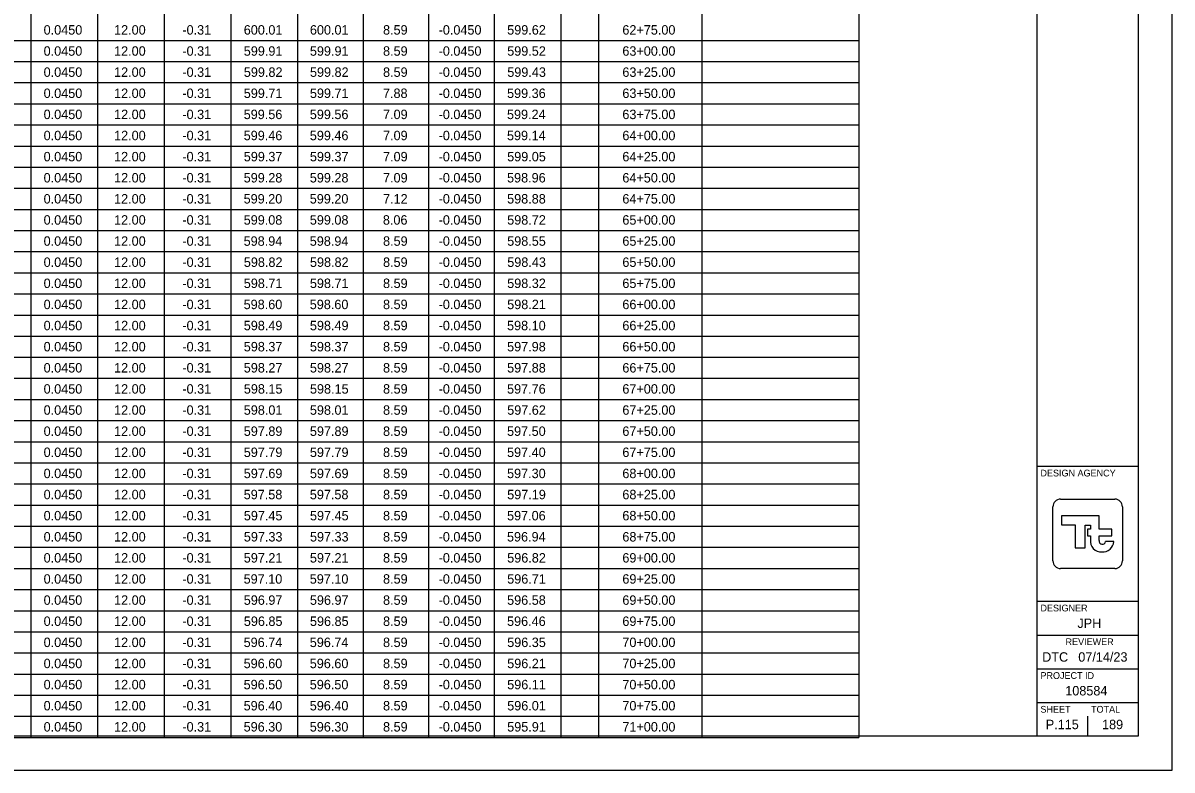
# Model space of a CAD drawing. Extents: x 0 to 34, y 0 to 22.
# Drawn here: x 16.97 to 34, y 0 to 11.07 of the extents above; entities that cross this region are included whole.
import ezdxf

# ---------------------------------------------------------------- set-up
doc = ezdxf.new("R2010")
doc.units = 0
for name, color, linetype in [('SH_Border', 7, 'Continuous'), ('SH_Cut_Line', 7, 'Continuous'), ('SH_Data', 7, 'Continuous'), ('SH_Text', 7, 'Continuous')]:
    doc.layers.add(name, color=color, linetype=linetype)

msp = doc.modelspace()

# ---------------------------------------------------------------- linework, layer by layer
at = {"layer": 'SH_Border'}
for p, q in [((32, 0.5), (32, 21.5)), ((32, 4.5), (33.5, 4.5)), ((32, 2.5), (33.5, 2.5)), ((32, 2), (33.5, 2)), ((32, 1.5), (33.5, 1.5)), ((32, 1), (33.5, 1))]:
    msp.add_line(p, q, dxfattribs=at)
msp.add_lwpolyline([(1.5, 21.5), (33.5, 21.5), (33.5, 0.5), (1.5, 0.5)], close=True, dxfattribs=at)
at = {"layer": 'SH_Cut_Line'}
msp.add_lwpolyline([(0, 0), (34, 0), (34, 22), (0, 22)], close=True, dxfattribs=at)
at = {"layer": 'SH_Data'}
for p, q in [((32.75, 3.5), (32.75, 3.5)), ((32.791, 3.415), (32.791, 3.415)), ((33.136, 3.385), (33.015, 3.385)), ((32.75, 0.5), (32.75, 0.8)), ((32.375, 0.675), (32.375, 0.675))]:
    msp.add_line(p, q, dxfattribs=at)
for points in [[(32.348, 4.014), (33.152, 4.014)], [(32.236, 3.099), (32.236, 3.901)], [(32.922, 3.399), (32.922, 3.47), (33.107, 3.47), (33.107, 3.568), (32.922, 3.568), (32.922, 3.768), (32.361, 3.768), (32.361, 3.632), (32.566, 3.632), (32.566, 3.294), (32.715, 3.294), (32.715, 3.63), (32.79, 3.63), (32.79, 3.568), (32.748, 3.568), (32.748, 3.47), (32.79, 3.47), (32.79, 3.415), (32.791, 3.415)], [(33.264, 3.901), (33.264, 3.099)], [(33.152, 2.986), (32.348, 2.986)]]:
    msp.add_lwpolyline(points, dxfattribs=at)
for centre, radius, start, end in [((32.348, 3.901), 0.113, 90, 180), ((33.152, 3.901), 0.113, 360, 90), ((32.949, 3.392), 0.16, 171.8856, 274.8323), ((32.968, 3.392), 0.0473, 171.8856, 350.9243), ((32.976, 3.392), 0.16, 265.1677, 357.3201), ((32.348, 3.099), 0.113, 180, 270), ((33.152, 3.099), 0.113, 270, 360)]:
    msp.add_arc(centre, radius, start, end, dxfattribs=at)
at = {"layer": 'SH_Text'}
for p, q in [((29.356, 21.5), (29.356, 0.484)), ((24.942, 20.396), (24.942, 0.484)), ((27.034, 20.396), (27.034, 0.484)), ((19.062, 19.853), (19.062, 0.484)), ((22.011, 19.853), (22.011, 0.484)), ((25.502, 19.853), (25.502, 0.484)), ((17.086, 19.54), (17.086, 0.484)), ((18.074, 19.54), (18.074, 0.484)), ((20.051, 19.54), (20.051, 0.484)), ((21.039, 19.54), (21.039, 0.484)), ((22.982, 19.54), (22.982, 0.484)), ((23.954, 19.54), (23.954, 0.484)), ((4.14, 10.811), (29.356, 10.811)), ((4.14, 10.498), (29.356, 10.498)), ((4.14, 10.185), (29.356, 10.185)), ((4.14, 9.872), (29.356, 9.872)), ((4.14, 9.559), (29.356, 9.559)), ((4.14, 9.246), (29.356, 9.246)), ((4.14, 8.933), (29.356, 8.933)), ((4.14, 8.62), (29.356, 8.62)), ((4.14, 8.307), (29.356, 8.307)), ((4.14, 7.994), (29.356, 7.994)), ((4.14, 7.681), (29.356, 7.681)), ((4.14, 7.368), (29.356, 7.368)), ((4.14, 7.055), (29.356, 7.055)), ((4.14, 6.742), (29.356, 6.742)), ((4.14, 6.429), (29.356, 6.429)), ((4.14, 6.116), (29.356, 6.116)), ((4.14, 5.804), (29.356, 5.804)), ((4.14, 5.491), (29.356, 5.491)), ((4.14, 5.178), (29.356, 5.178)), ((4.14, 4.865), (29.356, 4.865)), ((4.14, 4.552), (29.356, 4.552)), ((4.14, 4.239), (29.356, 4.239)), ((4.14, 3.926), (29.356, 3.926)), ((4.14, 3.613), (29.356, 3.613)), ((4.14, 3.3), (29.356, 3.3)), ((4.14, 2.987), (29.356, 2.987)), ((4.14, 2.674), (29.356, 2.674)), ((4.14, 2.361), (29.356, 2.361)), ((4.14, 2.048), (29.356, 2.048)), ((4.14, 1.735), (29.356, 1.735)), ((4.14, 1.422), (29.356, 1.422)), ((4.14, 1.109), (29.356, 1.109)), ((4.14, 0.796), (29.356, 0.796)), ((4.14, 0.484), (29.356, 0.484))]:
    msp.add_line(p, q, dxfattribs=at)

# ---------------------------------------------------------------- texts
at = {"layer": 'SH_Data'}
for s, height, p in [('DESIGN AGENCY', 0.1, (32.05, 4.35)), ('DESIGNER', 0.1, (32.05, 2.35)), ('JPH', 0.14, (32.598, 2.105)), ('REVIEWER', 0.1, (32.422, 1.85)), ('DTC', 0.14, (32.076, 1.605)), ('07/14/23', 0.14, (32.611, 1.605)), ('PROJECT ID', 0.1, (32.05, 1.35)), ('108584', 0.14, (32.418, 1.105)), ('SHEET', 0.1, (32.05, 0.85)), ('TOTAL', 0.1, (32.8, 0.85)), ('P.115', 0.14, (32.129, 0.605)), ('189', 0.14, (32.963, 0.605))]:
    msp.add_text(s, height=height, dxfattribs=at).set_placement(p)
at = {"layer": 'SH_Text'}
for s, p in [('0.0450', (17.277, 10.897)), ('12.00', (18.321, 10.897)), ('-0.31', (19.333, 10.897)), ('600.01', (20.243, 10.897)), ('600.01', (21.223, 10.897)), ('8.59', (22.307, 10.897)), ('-0.0450', (23.131, 10.897)), ('599.62', (24.147, 10.897)), ('62+75.00', (25.854, 10.897)), ('0.0450', (17.277, 10.584)), ('12.00', (18.321, 10.584)), ('-0.31', (19.333, 10.584)), ('599.91', (20.243, 10.584)), ('599.91', (21.223, 10.584)), ('8.59', (22.307, 10.584)), ('-0.0450', (23.131, 10.584)), ('599.52', (24.147, 10.584)), ('63+00.00', (25.854, 10.584)), ('0.0450', (17.277, 10.271)), ('12.00', (18.321, 10.271)), ('-0.31', (19.333, 10.271)), ('599.82', (20.244, 10.271)), ('599.82', (21.224, 10.271)), ('8.59', (22.307, 10.271)), ('-0.0450', (23.131, 10.271)), ('599.43', (24.148, 10.271)), ('63+25.00', (25.854, 10.271)), ('0.0450', (17.277, 9.958)), ('12.00', (18.321, 9.958)), ('-0.31', (19.333, 9.958)), ('599.71', (20.243, 9.958)), ('599.71', (21.223, 9.958)), ('7.88', (22.306, 9.958)), ('-0.0450', (23.131, 9.958)), ('599.36', (24.145, 9.958)), ('63+50.00', (25.854, 9.958)), ('0.0450', (17.277, 9.645)), ('12.00', (18.321, 9.645)), ('-0.31', (19.333, 9.645)), ('599.56', (20.242, 9.645)), ('599.56', (21.222, 9.645)), ('7.09', (22.307, 9.645)), ('-0.0450', (23.131, 9.645)), ('599.24', (24.144, 9.645)), ('63+75.00', (25.854, 9.645)), ('0.0450', (17.277, 9.332)), ('12.00', (18.321, 9.332)), ('-0.31', (19.333, 9.332)), ('599.46', (20.242, 9.332)), ('599.46', (21.222, 9.332)), ('7.09', (22.307, 9.332)), ('-0.0450', (23.131, 9.332)), ('599.14', (24.144, 9.332)), ('64+00.00', (25.854, 9.332)), ('0.0450', (17.277, 9.019)), ('12.00', (18.321, 9.019)), ('-0.31', (19.333, 9.019)), ('599.37', (20.243, 9.019)), ('599.37', (21.223, 9.019)), ('7.09', (22.307, 9.019)), ('-0.0450', (23.131, 9.019)), ('599.05', (24.147, 9.019)), ('64+25.00', (25.854, 9.019)), ('0.0450', (17.277, 8.706)), ('12.00', (18.321, 8.706)), ('-0.31', (19.333, 8.706)), ('599.28', (20.242, 8.706)), ('599.28', (21.222, 8.706)), ('7.09', (22.307, 8.706)), ('-0.0450', (23.131, 8.706)), ('598.96', (24.145, 8.706)), ('64+50.00', (25.854, 8.706)), ('0.0450', (17.277, 8.394)), ('12.00', (18.321, 8.394)), ('-0.31', (19.333, 8.394)), ('599.20', (20.241, 8.394)), ('599.20', (21.221, 8.394)), ('7.12', (22.307, 8.394)), ('-0.0450', (23.131, 8.394)), ('598.88', (24.146, 8.394)), ('64+75.00', (25.854, 8.394)), ('0.0450', (17.277, 8.081)), ('12.00', (18.321, 8.081)), ('-0.31', (19.333, 8.081)), ('599.08', (20.242, 8.081)), ('599.08', (21.222, 8.081)), ('8.06', (22.305, 8.081)), ('-0.0450', (23.131, 8.081)), ('598.72', (24.147, 8.081)), ('65+00.00', (25.854, 8.081)), ('0.0450', (17.277, 7.768)), ('12.00', (18.321, 7.768)), ('-0.31', (19.333, 7.768)), ('598.94', (20.241, 7.768)), ('598.94', (21.221, 7.768)), ('8.59', (22.307, 7.768)), ('-0.0450', (23.131, 7.768)), ('598.55', (24.147, 7.768)), ('65+25.00', (25.854, 7.768)), ('0.0450', (17.277, 7.455)), ('12.00', (18.321, 7.455)), ('-0.31', (19.333, 7.455)), ('598.82', (20.244, 7.455)), ('598.82', (21.224, 7.455)), ('8.59', (22.307, 7.455)), ('-0.0450', (23.131, 7.455)), ('598.43', (24.148, 7.455)), ('65+50.00', (25.854, 7.455)), ('0.0450', (17.277, 7.142)), ('12.00', (18.321, 7.142)), ('-0.31', (19.333, 7.142)), ('598.71', (20.243, 7.142)), ('598.71', (21.223, 7.142)), ('8.59', (22.307, 7.142)), ('-0.0450', (23.131, 7.142)), ('598.32', (24.147, 7.142)), ('65+75.00', (25.854, 7.142)), ('0.0450', (17.277, 6.829)), ('12.00', (18.321, 6.829)), ('-0.31', (19.333, 6.829)), ('598.60', (20.241, 6.829)), ('598.60', (21.221, 6.829)), ('8.59', (22.307, 6.829)), ('-0.0450', (23.131, 6.829)), ('598.21', (24.147, 6.829)), ('66+00.00', (25.854, 6.829)), ('0.0450', (17.277, 6.516)), ('12.00', (18.321, 6.516)), ('-0.31', (19.333, 6.516)), ('598.49', (20.243, 6.516)), ('598.49', (21.223, 6.516)), ('8.59', (22.307, 6.516)), ('-0.0450', (23.131, 6.516)), ('598.10', (24.145, 6.516)), ('66+25.00', (25.854, 6.516)), ('0.0450', (17.277, 6.203)), ('12.00', (18.321, 6.203)), ('-0.31', (19.333, 6.203)), ('598.37', (20.243, 6.203)), ('598.37', (21.223, 6.203)), ('8.59', (22.307, 6.203)), ('-0.0450', (23.131, 6.203)), ('597.98', (24.146, 6.203)), ('66+50.00', (25.854, 6.203)), ('0.0450', (17.277, 5.89)), ('12.00', (18.321, 5.89)), ('-0.31', (19.333, 5.89)), ('598.27', (20.243, 5.89)), ('598.27', (21.223, 5.89)), ('8.59', (22.307, 5.89)), ('-0.0450', (23.131, 5.89)), ('597.88', (24.146, 5.89)), ('66+75.00', (25.854, 5.89)), ('0.0450', (17.277, 5.577)), ('12.00', (18.321, 5.577)), ('-0.31', (19.333, 5.577)), ('598.15', (20.244, 5.577)), ('598.15', (21.224, 5.577)), ('8.59', (22.307, 5.577)), ('-0.0450', (23.131, 5.577)), ('597.76', (24.145, 5.577)), ('67+00.00', (25.854, 5.577)), ('0.0450', (17.277, 5.264)), ('12.00', (18.321, 5.264)), ('-0.31', (19.333, 5.264)), ('598.01', (20.243, 5.264)), ('598.01', (21.223, 5.264)), ('8.59', (22.307, 5.264)), ('-0.0450', (23.131, 5.264)), ('597.62', (24.147, 5.264)), ('67+25.00', (25.854, 5.264)), ('0.0450', (17.277, 4.951)), ('12.00', (18.321, 4.951)), ('-0.31', (19.333, 4.951)), ('597.89', (20.243, 4.951)), ('597.89', (21.223, 4.951)), ('8.59', (22.307, 4.951)), ('-0.0450', (23.131, 4.951)), ('597.50', (24.145, 4.951)), ('67+50.00', (25.854, 4.951)), ('0.0450', (17.277, 4.638)), ('12.00', (18.321, 4.638)), ('-0.31', (19.333, 4.638)), ('597.79', (20.243, 4.638)), ('597.79', (21.223, 4.638)), ('8.59', (22.307, 4.638)), ('-0.0450', (23.131, 4.638)), ('597.40', (24.145, 4.638)), ('67+75.00', (25.854, 4.638)), ('0.0450', (17.277, 4.325)), ('12.00', (18.321, 4.325)), ('-0.31', (19.333, 4.325)), ('597.69', (20.243, 4.325)), ('597.69', (21.223, 4.325)), ('8.59', (22.307, 4.325)), ('-0.0450', (23.131, 4.325)), ('597.30', (24.145, 4.325)), ('68+00.00', (25.854, 4.325)), ('0.0450', (17.277, 4.012)), ('12.00', (18.321, 4.012)), ('-0.31', (19.333, 4.012)), ('597.58', (20.242, 4.012)), ('597.58', (21.222, 4.012)), ('8.59', (22.307, 4.012)), ('-0.0450', (23.131, 4.012)), ('597.19', (24.147, 4.012)), ('68+25.00', (25.854, 4.012)), ('0.0450', (17.277, 3.699)), ('12.00', (18.321, 3.699)), ('-0.31', (19.333, 3.699)), ('597.45', (20.244, 3.699)), ('597.45', (21.224, 3.699)), ('8.59', (22.307, 3.699)), ('-0.0450', (23.131, 3.699)), ('597.06', (24.145, 3.699)), ('68+50.00', (25.854, 3.699)), ('0.0450', (17.277, 3.386)), ('12.00', (18.321, 3.386)), ('-0.31', (19.333, 3.386)), ('597.33', (20.244, 3.386)), ('597.33', (21.224, 3.386)), ('8.59', (22.307, 3.386)), ('-0.0450', (23.131, 3.386)), ('596.94', (24.144, 3.386)), ('68+75.00', (25.854, 3.386)), ('0.0450', (17.277, 3.074)), ('12.00', (18.321, 3.074)), ('-0.31', (19.333, 3.074)), ('597.21', (20.243, 3.074)), ('597.21', (21.223, 3.074)), ('8.59', (22.307, 3.074)), ('-0.0450', (23.131, 3.074)), ('596.82', (24.147, 3.074)), ('69+00.00', (25.854, 3.074)), ('0.0450', (17.277, 2.761)), ('12.00', (18.321, 2.761)), ('-0.31', (19.333, 2.761)), ('597.10', (20.241, 2.761)), ('597.10', (21.221, 2.761)), ('8.59', (22.307, 2.761)), ('-0.0450', (23.131, 2.761)), ('596.71', (24.147, 2.761)), ('69+25.00', (25.854, 2.761)), ('0.0450', (17.277, 2.448)), ('12.00', (18.321, 2.448)), ('-0.31', (19.333, 2.448)), ('596.97', (20.243, 2.448)), ('596.97', (21.223, 2.448)), ('8.59', (22.307, 2.448)), ('-0.0450', (23.131, 2.448)), ('596.58', (24.146, 2.448)), ('69+50.00', (25.854, 2.448)), ('0.0450', (17.277, 2.135)), ('12.00', (18.321, 2.135)), ('-0.31', (19.333, 2.135)), ('596.85', (20.244, 2.135)), ('596.85', (21.224, 2.135)), ('8.59', (22.307, 2.135)), ('-0.0450', (23.131, 2.135)), ('596.46', (24.145, 2.135)), ('69+75.00', (25.854, 2.135)), ('0.0450', (17.277, 1.822)), ('12.00', (18.321, 1.822)), ('-0.31', (19.333, 1.822)), ('596.74', (20.241, 1.822)), ('596.74', (21.221, 1.822)), ('8.59', (22.307, 1.822)), ('-0.0450', (23.131, 1.822)), ('596.35', (24.147, 1.822)), ('70+00.00', (25.854, 1.822)), ('0.0450', (17.277, 1.509)), ('12.00', (18.321, 1.509)), ('-0.31', (19.333, 1.509)), ('596.60', (20.241, 1.509)), ('596.60', (21.221, 1.509)), ('8.59', (22.307, 1.509)), ('-0.0450', (23.131, 1.509)), ('596.21', (24.147, 1.509)), ('70+25.00', (25.854, 1.509)), ('0.0450', (17.277, 1.196)), ('12.00', (18.321, 1.196)), ('-0.31', (19.333, 1.196)), ('596.50', (20.241, 1.196)), ('596.50', (21.221, 1.196)), ('8.59', (22.307, 1.196)), ('-0.0450', (23.131, 1.196)), ('596.11', (24.147, 1.196)), ('70+50.00', (25.854, 1.196)), ('0.0450', (17.277, 0.883)), ('12.00', (18.321, 0.883)), ('-0.31', (19.333, 0.883)), ('596.40', (20.241, 0.883)), ('596.40', (21.221, 0.883)), ('8.59', (22.307, 0.883)), ('-0.0450', (23.131, 0.883)), ('596.01', (24.147, 0.883)), ('70+75.00', (25.854, 0.883)), ('0.0450', (17.277, 0.57)), ('12.00', (18.321, 0.57)), ('-0.31', (19.333, 0.57)), ('596.30', (20.241, 0.57)), ('596.30', (21.221, 0.57)), ('8.59', (22.307, 0.57)), ('-0.0450', (23.131, 0.57)), ('595.91', (24.147, 0.57)), ('71+00.00', (25.854, 0.57))]:
    msp.add_text(s, height=0.14, dxfattribs=at).set_placement(p)

doc.saveas('drawing.dxf')
